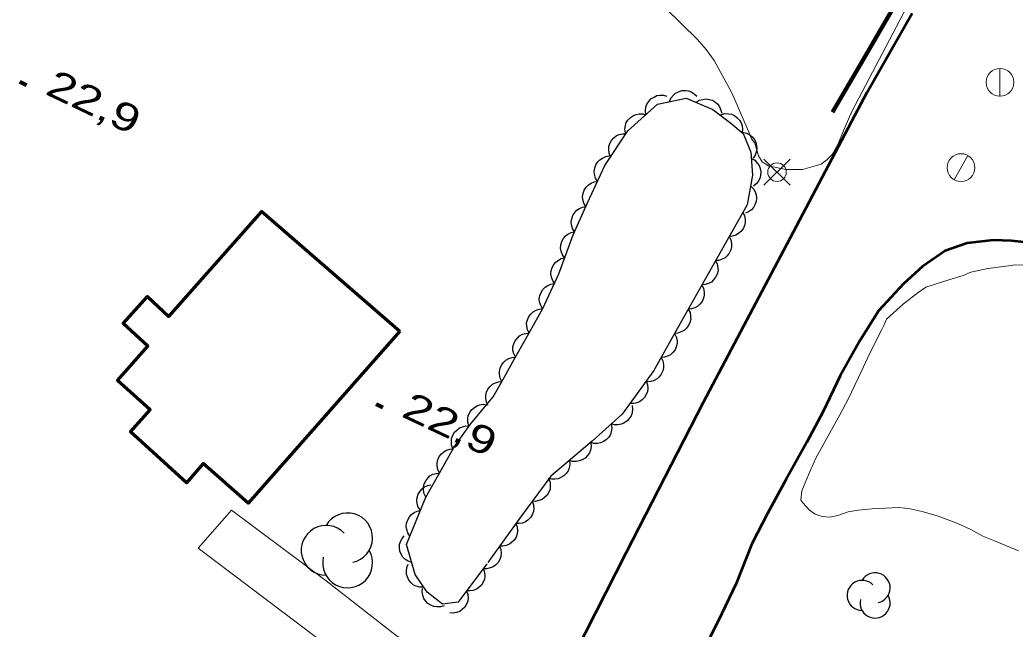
# Model space of a CAD drawing. Extents: x 356765 to 358572, y 5103174 to 5104650.
# Drawn here: x 357232.5 to 357286.2, y 5104019.8 to 5104052.7 of the extents above; entities that cross this region are included whole.
import ezdxf

# ---------------------------------------------------------------- set-up
doc = ezdxf.new("R2010")
doc.units = 0
doc.header["$LTSCALE"] = 0.6
doc.linetypes.add('DOT_DASHED', pattern=[7.7, 5, -1.2, 0.3, -1.2])
doc.linetypes.add('LONG_DASHED', pattern=[7.5, 6, -1.5])
for name, color, linetype, lineweight in [('19', 7, 'Continuous', 13), ('2', 7, 'Continuous', 13), ('21', 7, 'Continuous', 53), ('3', 7, 'Continuous', 140), ('31', 7, 'Continuous', 70), ('36', 7, 'Continuous', 13), ('44', 7, 'Continuous', 25)]:
    doc.layers.add(name, color=color, linetype=linetype, lineweight=lineweight)

msp = doc.modelspace()

# ---------------------------------------------------------------- linework, layer by layer
at = {"layer": '19'}
msp.add_lwpolyline([(357258.19, 5104009.55), (357257.02, 5104011.41), (357255.59, 5104013.33), (357253, 5104015.99), (357242.14, 5104024.2), (357243.93, 5104026.26), (357249.05, 5104022.43), (357252.82, 5104019.49), (357255.94, 5104017.56), (357257.33, 5104016.89), (357258.34, 5104016.43), (357258.98, 5104016.36), (357259.36, 5104016.34), (357259.59, 5104016.41), (357261.4, 5104016.4)], dxfattribs=at)
at = {"layer": '2'}
for points in [[(357271.83, 5104046.76), (357272.01, 5104046.3), (357272.19, 5104046.07), (357272.39, 5104045.38), (357272.58, 5104045.07), (357272.93, 5104044.84), (357273.86, 5104044.65), (357274.76, 5104044.65), (357275.77, 5104044.94), (357276.07, 5104045.18), (357276.37, 5104045.46), (357276.67, 5104046), (357277.06, 5104046.96), (357277.42, 5104047.78), (357280.2, 5104053.05), (357281.49, 5104055.63), (357282.67, 5104057.84), (357283.51, 5104059.57), (357284.25, 5104061.28), (357285.15, 5104063.69), (357286.91, 5104068.94)], [(357286.76, 5104039.48), (357286.21, 5104039.5), (357286.03, 5104039.47), (357284.76, 5104039.3), (357283.85, 5104039.11), (357283.44, 5104038.93), (357282.66, 5104038.7), (357281.42, 5104038.29), (357281, 5104038), (357280.22, 5104037.4), (357279.3, 5104036.57), (357279.15, 5104036.22), (357279.04, 5104036.01), (357278.41, 5104034.76), (357277.79, 5104033.41), (357277.23, 5104032.24), (357276.77, 5104031.4), (357276.14, 5104030.26), (357275.5, 5104029.09), (357275.17, 5104028.38), (357274.72, 5104027.29), (357274.67, 5104026.8), (357274.78, 5104026.65), (357275.14, 5104026.26), (357275.45, 5104026.04), (357275.82, 5104025.91)], [(357286.76, 5104039.48), (357286.21, 5104039.5), (357286.03, 5104039.47), (357284.76, 5104039.3), (357283.85, 5104039.11), (357283.44, 5104038.93), (357282.66, 5104038.7), (357281.42, 5104038.29), (357281, 5104038), (357280.22, 5104037.4), (357279.3, 5104036.57), (357279.15, 5104036.22), (357279.04, 5104036.01), (357278.41, 5104034.76), (357277.79, 5104033.41), (357277.23, 5104032.24), (357276.77, 5104031.4), (357276.14, 5104030.26), (357275.5, 5104029.09), (357275.17, 5104028.38), (357274.72, 5104027.29), (357274.67, 5104026.8), (357274.78, 5104026.65), (357275.14, 5104026.26), (357275.45, 5104026.04), (357275.82, 5104025.91)], [(357275.82, 5104025.91), (357275.82, 5104025.91), (357276.22, 5104025.88), (357276.67, 5104025.97), (357277.23, 5104026.17), (357277.76, 5104026.26), (357278.53, 5104026.32), (357279.96, 5104026.4), (357280.58, 5104026.33), (357281.22, 5104026.19), (357282.08, 5104025.93), (357283.09, 5104025.55), (357283.85, 5104025.21), (357284.5, 5104024.84), (357285.13, 5104024.59), (357286.42, 5104024.05)], [(357275.82, 5104025.91), (357276.22, 5104025.88), (357276.67, 5104025.97), (357277.23, 5104026.17), (357277.76, 5104026.26), (357278.53, 5104026.32), (357279.96, 5104026.4), (357280.58, 5104026.33), (357281.22, 5104026.19), (357282.08, 5104025.93), (357283.09, 5104025.55), (357283.85, 5104025.21), (357284.5, 5104024.84), (357285.13, 5104024.59), (357286.42, 5104024.05)]]:
    msp.add_lwpolyline(points, dxfattribs=at)
at = {"layer": '2', "linetype": 'LONG_DASHED'}
msp.add_lwpolyline([(357267.37, 5104053.37), (357269.1, 5104051.67), (357269.57, 5104051.13), (357269.99, 5104050.53), (357270.95, 5104048.8), (357271.83, 5104046.76)], dxfattribs=at)
at = {"layer": '21', "linetype": 'LONG_DASHED', "lineweight": 140}
msp.add_lwpolyline([(357282.55, 5104058.36), (357281.01, 5104055.71), (357279.47, 5104053.05), (357277.93, 5104050.4), (357276.39, 5104047.75)], dxfattribs=at)
at = {"layer": '21'}
for points in [[(357235, 5103902.34), (357236.8, 5103914.18), (357238.16, 5103922.98), (357240.84, 5103943.53), (357241.93, 5103951.26), (357243.11, 5103959.18), (357244.3, 5103966.44), (357246.54, 5103976.17), (357248.33, 5103983.55), (357249.72, 5103987.87), (357253.83, 5103998.68), (357255.78, 5104004.15), (357260.07, 5104013.78), (357261.4, 5104016.4), (357265.26, 5104023.99), (357269.42, 5104032.09), (357274.09, 5104040.95), (357277.93, 5104048.22), (357278.25, 5104048.83), (357280.69, 5104053.09)], [(357288.05, 5104040.59), (357286.04, 5104040.8), (357285.07, 5104040.84), (357283.66, 5104040.67), (357282.47, 5104040.25), (357281.24, 5104039.41), (357280.21, 5104038.48), (357278.89, 5104037.03), (357277.88, 5104035.43), (357276.79, 5104033.51), (357275.88, 5104031.58), (357274.99, 5104029.92), (357273.86, 5104027.9), (357272.87, 5104026.08), (357272.02, 5104024.43), (357271.18, 5104022.3), (357270.4, 5104020.67), (357269.19, 5104018.19)]]:
    msp.add_lwpolyline(points, dxfattribs=at)
at = {"layer": '3'}
for p, q in [((357232.51, 5104049.38), (357232.87, 5104049.21)), ((357251.74, 5104031.97), (357252.1, 5104031.8))]:
    msp.add_line(p, q, dxfattribs=at)
at = {"layer": '31'}
msp.add_lwpolyline([(357253.03, 5104035.92), (357244.84, 5104026.63), (357242.4, 5104028.78), (357241.51, 5104027.73), (357238.48, 5104030.48), (357239.55, 5104031.67), (357237.78, 5104033.26), (357239.41, 5104035.11), (357238.08, 5104036.34), (357239.4, 5104037.79), (357240.55, 5104036.72), (357245.58, 5104042.38), (357253.03, 5104035.92)], close=True, dxfattribs=at)
at = {"layer": '36'}
for p, q in [((357285.42, 5104048.6), (357285.42, 5104050.1)), ((357282.95, 5104044.1), (357283.69, 5104045.4)), ((357274.09, 5104043.8), (357272.68, 5104045.21)), ((357272.68, 5104043.8), (357274.09, 5104045.21))]:
    msp.add_line(p, q, dxfattribs=at)
for centre, radius in [((357285.4259, 5104049.3604), 0.75), ((357283.3194, 5104044.755), 0.75), ((357273.3868, 5104044.5074), 0.5)]:
    msp.add_circle(centre, radius, dxfattribs=at)
at = {"layer": '44'}
for points in [[(357266.31, 5104047.61), (357266.28, 5104047.82), (357266.31, 5104048.02), (357266.36, 5104048.18), (357266.46, 5104048.33), (357266.58, 5104048.46), (357266.75, 5104048.56), (357266.89, 5104048.64), (357267.07, 5104048.66), (357267.25, 5104048.66), (357267.43, 5104048.62)], [(357267.58, 5104048.31), (357267.66, 5104048.51), (357267.79, 5104048.66), (357267.91, 5104048.78), (357268.07, 5104048.85), (357268.24, 5104048.91), (357268.44, 5104048.91), (357268.6, 5104048.9), (357268.76, 5104048.84), (357268.92, 5104048.74), (357269.05, 5104048.62)], [(357269.02, 5104048.28), (357269.19, 5104048.39), (357269.39, 5104048.44), (357269.55, 5104048.47), (357269.72, 5104048.44), (357269.9, 5104048.39), (357270.06, 5104048.28), (357270.19, 5104048.18), (357270.28, 5104048.03), (357270.36, 5104047.86), (357270.4, 5104047.69)], [(357265.2, 5104046.61), (357265.17, 5104046.82), (357265.2, 5104047.02), (357265.25, 5104047.18), (357265.34, 5104047.32), (357265.47, 5104047.46), (357265.63, 5104047.56), (357265.78, 5104047.63), (357265.95, 5104047.66), (357266.14, 5104047.66), (357266.31, 5104047.61)], [(357270.36, 5104047.61), (357270.56, 5104047.67), (357270.76, 5104047.66), (357270.93, 5104047.64), (357271.09, 5104047.56), (357271.24, 5104047.45), (357271.36, 5104047.31), (357271.45, 5104047.17), (357271.5, 5104047), (357271.52, 5104046.82), (357271.5, 5104046.64)], [(357264.4, 5104045.33), (357264.32, 5104045.53), (357264.3, 5104045.73), (357264.31, 5104045.89), (357264.36, 5104046.06), (357264.45, 5104046.22), (357264.58, 5104046.36), (357264.71, 5104046.47), (357264.87, 5104046.54), (357265.05, 5104046.58), (357265.23, 5104046.58)], [(357271.53, 5104046.66), (357271.74, 5104046.62), (357271.91, 5104046.52), (357272.05, 5104046.42), (357272.15, 5104046.28), (357272.24, 5104046.12), (357272.28, 5104045.93), (357272.3, 5104045.77), (357272.26, 5104045.59), (357272.2, 5104045.42), (357272.1, 5104045.27)], [(357263.7, 5104044.01), (357263.59, 5104044.19), (357263.54, 5104044.39), (357263.52, 5104044.55), (357263.55, 5104044.73), (357263.61, 5104044.9), (357263.72, 5104045.06), (357263.82, 5104045.18), (357263.97, 5104045.27), (357264.14, 5104045.35), (357264.32, 5104045.38)], [(357272, 5104045.25), (357272.18, 5104045.15), (357272.32, 5104045), (357272.42, 5104044.87), (357272.48, 5104044.7), (357272.51, 5104044.52), (357272.49, 5104044.33), (357272.46, 5104044.17), (357272.37, 5104044.01), (357272.26, 5104043.87), (357272.12, 5104043.75)], [(357263.07, 5104042.65), (357262.96, 5104042.83), (357262.91, 5104043.03), (357262.89, 5104043.19), (357262.92, 5104043.36), (357262.98, 5104043.54), (357263.09, 5104043.7), (357263.2, 5104043.82), (357263.35, 5104043.91), (357263.52, 5104043.98), (357263.7, 5104044.01)], [(357271.96, 5104043.76), (357272.11, 5104043.61), (357272.2, 5104043.44), (357272.26, 5104043.28), (357272.28, 5104043.11), (357272.26, 5104042.92), (357272.19, 5104042.74), (357272.12, 5104042.6), (357272, 5104042.47), (357271.85, 5104042.36), (357271.68, 5104042.29)], [(357262.45, 5104041.28), (357262.34, 5104041.46), (357262.29, 5104041.66), (357262.27, 5104041.82), (357262.3, 5104041.99), (357262.36, 5104042.17), (357262.47, 5104042.33), (357262.57, 5104042.45), (357262.72, 5104042.55), (357262.89, 5104042.62), (357263.07, 5104042.65)], [(357271.54, 5104042.34), (357271.63, 5104042.15), (357271.67, 5104041.95), (357271.67, 5104041.79), (357271.63, 5104041.62), (357271.55, 5104041.45), (357271.43, 5104041.3), (357271.31, 5104041.19), (357271.16, 5104041.1), (357270.98, 5104041.05), (357270.8, 5104041.03)], [(357261.92, 5104039.88), (357261.8, 5104040.05), (357261.73, 5104040.24), (357261.7, 5104040.4), (357261.72, 5104040.58), (357261.77, 5104040.76), (357261.86, 5104040.92), (357261.96, 5104041.06), (357262.1, 5104041.16), (357262.27, 5104041.24), (357262.44, 5104041.29)], [(357270.8, 5104041.03), (357270.89, 5104040.85), (357270.93, 5104040.65), (357270.93, 5104040.48), (357270.89, 5104040.31), (357270.81, 5104040.14), (357270.69, 5104039.99), (357270.58, 5104039.88), (357270.42, 5104039.8), (357270.24, 5104039.74), (357270.06, 5104039.73)], [(357261.4, 5104038.47), (357261.28, 5104038.64), (357261.21, 5104038.84), (357261.18, 5104039), (357261.2, 5104039.17), (357261.25, 5104039.35), (357261.34, 5104039.52), (357261.44, 5104039.65), (357261.58, 5104039.75), (357261.74, 5104039.84), (357261.92, 5104039.88)], [(357270.06, 5104039.73), (357270.16, 5104039.54), (357270.19, 5104039.34), (357270.2, 5104039.17), (357270.15, 5104039), (357270.07, 5104038.84), (357269.95, 5104038.69), (357269.84, 5104038.57), (357269.68, 5104038.49), (357269.51, 5104038.44), (357269.33, 5104038.42)], [(357260.73, 5104037.13), (357260.63, 5104037.3), (357260.57, 5104037.5), (357260.55, 5104037.67), (357260.58, 5104037.84), (357260.65, 5104038.01), (357260.75, 5104038.17), (357260.86, 5104038.3), (357261.01, 5104038.39), (357261.18, 5104038.46), (357261.36, 5104038.49)], [(357269.33, 5104038.42), (357269.42, 5104038.23), (357269.45, 5104038.03), (357269.46, 5104037.87), (357269.42, 5104037.7), (357269.34, 5104037.53), (357269.22, 5104037.38), (357269.11, 5104037.27), (357268.95, 5104037.18), (357268.77, 5104037.13), (357268.59, 5104037.11)], [(357260, 5104035.82), (357259.91, 5104036.01), (357259.87, 5104036.21), (357259.86, 5104036.37), (357259.91, 5104036.54), (357259.98, 5104036.71), (357260.11, 5104036.86), (357260.22, 5104036.97), (357260.38, 5104037.05), (357260.55, 5104037.11), (357260.73, 5104037.13)], [(357268.59, 5104037.11), (357268.69, 5104036.93), (357268.72, 5104036.73), (357268.73, 5104036.56), (357268.68, 5104036.39), (357268.61, 5104036.22), (357268.49, 5104036.07), (357268.37, 5104035.96), (357268.22, 5104035.88), (357268.04, 5104035.82), (357267.86, 5104035.8)], [(357259.26, 5104034.51), (357259.17, 5104034.7), (357259.13, 5104034.9), (357259.13, 5104035.07), (357259.17, 5104035.24), (357259.25, 5104035.4), (357259.37, 5104035.55), (357259.49, 5104035.67), (357259.64, 5104035.75), (357259.82, 5104035.8), (357260, 5104035.82)], [(357267.86, 5104035.8), (357267.95, 5104035.62), (357267.99, 5104035.42), (357268, 5104035.25), (357267.95, 5104035.08), (357267.88, 5104034.91), (357267.76, 5104034.76), (357267.64, 5104034.65), (357267.48, 5104034.57), (357267.31, 5104034.51), (357267.13, 5104034.49)], [(357258.53, 5104033.2), (357258.44, 5104033.39), (357258.4, 5104033.59), (357258.4, 5104033.75), (357258.44, 5104033.92), (357258.51, 5104034.09), (357258.63, 5104034.24), (357258.75, 5104034.36), (357258.9, 5104034.44), (357259.08, 5104034.5), (357259.26, 5104034.51)], [(357267.13, 5104034.49), (357267.22, 5104034.31), (357267.26, 5104034.11), (357267.26, 5104033.94), (357267.22, 5104033.77), (357267.14, 5104033.6), (357267.02, 5104033.45), (357266.91, 5104033.34), (357266.75, 5104033.26), (357266.58, 5104033.2), (357266.4, 5104033.19)], [(357257.79, 5104031.9), (357257.7, 5104032.08), (357257.67, 5104032.28), (357257.66, 5104032.45), (357257.71, 5104032.62), (357257.78, 5104032.79), (357257.9, 5104032.94), (357258.02, 5104033.05), (357258.18, 5104033.13), (357258.35, 5104033.19), (357258.53, 5104033.2)], [(357266.33, 5104033.23), (357266.4, 5104033.03), (357266.41, 5104032.83), (357266.4, 5104032.67), (357266.33, 5104032.5), (357266.24, 5104032.34), (357266.1, 5104032.21), (357265.97, 5104032.11), (357265.81, 5104032.05), (357265.63, 5104032.01), (357265.45, 5104032.02)], [(357256.75, 5104030.8), (357256.7, 5104031), (357256.7, 5104031.2), (357256.72, 5104031.36), (357256.8, 5104031.52), (357256.9, 5104031.68), (357257.05, 5104031.8), (357257.18, 5104031.89), (357257.35, 5104031.94), (357257.53, 5104031.97), (357257.71, 5104031.95)], [(357265.56, 5104031.91), (357265.59, 5104031.71), (357265.56, 5104031.51), (357265.51, 5104031.35), (357265.41, 5104031.2), (357265.29, 5104031.07), (357265.12, 5104030.96), (357264.98, 5104030.89), (357264.8, 5104030.87), (357264.62, 5104030.87), (357264.44, 5104030.91)], [(357264.44, 5104030.91), (357264.47, 5104030.7), (357264.44, 5104030.5), (357264.39, 5104030.34), (357264.3, 5104030.2), (357264.17, 5104030.06), (357264.01, 5104029.96), (357263.86, 5104029.89), (357263.69, 5104029.86), (357263.5, 5104029.86), (357263.33, 5104029.91)], [(357255.89, 5104029.57), (357255.82, 5104029.77), (357255.81, 5104029.97), (357255.82, 5104030.13), (357255.88, 5104030.3), (357255.97, 5104030.46), (357256.11, 5104030.59), (357256.24, 5104030.7), (357256.4, 5104030.76), (357256.58, 5104030.8), (357256.76, 5104030.79)], [(357263.33, 5104029.91), (357263.35, 5104029.7), (357263.31, 5104029.5), (357263.26, 5104029.35), (357263.16, 5104029.2), (357263.03, 5104029.07), (357262.86, 5104028.97), (357262.71, 5104028.91), (357262.54, 5104028.88), (357262.35, 5104028.89), (357262.18, 5104028.94)], [(357255.16, 5104028.26), (357255.07, 5104028.45), (357255.04, 5104028.65), (357255.03, 5104028.81), (357255.07, 5104028.98), (357255.15, 5104029.15), (357255.27, 5104029.3), (357255.39, 5104029.41), (357255.54, 5104029.49), (357255.72, 5104029.55), (357255.9, 5104029.57)], [(357262.18, 5104028.94), (357262.2, 5104028.73), (357262.16, 5104028.53), (357262.11, 5104028.38), (357262.01, 5104028.23), (357261.88, 5104028.1), (357261.72, 5104028.01), (357261.57, 5104027.94), (357261.39, 5104027.92), (357261.21, 5104027.93), (357261.03, 5104027.97)], [(357254.43, 5104026.95), (357254.34, 5104027.14), (357254.3, 5104027.34), (357254.3, 5104027.5), (357254.34, 5104027.67), (357254.42, 5104027.84), (357254.54, 5104027.99), (357254.65, 5104028.11), (357254.81, 5104028.19), (357254.98, 5104028.24), (357255.16, 5104028.26)], [(357254.14, 5104026.23), (357254.02, 5104026.41), (357253.96, 5104026.6), (357253.94, 5104026.77), (357253.96, 5104026.94), (357254.01, 5104027.12), (357254.12, 5104027.28), (357254.22, 5104027.41), (357254.36, 5104027.51), (357254.53, 5104027.59), (357254.7, 5104027.62)], [(357261.06, 5104027.95), (357261.13, 5104027.75), (357261.14, 5104027.55), (357261.13, 5104027.38), (357261.06, 5104027.22), (357260.97, 5104027.06), (357260.83, 5104026.93), (357260.7, 5104026.83), (357260.53, 5104026.77), (357260.35, 5104026.73), (357260.17, 5104026.74)], [(357260.17, 5104026.74), (357260.24, 5104026.54), (357260.25, 5104026.34), (357260.24, 5104026.18), (357260.17, 5104026.01), (357260.08, 5104025.85), (357259.94, 5104025.72), (357259.81, 5104025.62), (357259.64, 5104025.56), (357259.46, 5104025.53), (357259.28, 5104025.53)], [(357253.57, 5104024.85), (357253.46, 5104025.02), (357253.4, 5104025.21), (357253.37, 5104025.38), (357253.39, 5104025.55), (357253.45, 5104025.73), (357253.55, 5104025.89), (357253.65, 5104026.02), (357253.79, 5104026.12), (357253.96, 5104026.2), (357254.14, 5104026.23)], [(357259.29, 5104025.53), (357259.36, 5104025.33), (357259.37, 5104025.13), (357259.36, 5104024.97), (357259.3, 5104024.8), (357259.2, 5104024.64), (357259.06, 5104024.51), (357258.94, 5104024.41), (357258.77, 5104024.34), (357258.59, 5104024.31), (357258.41, 5104024.31)], [(357253.67, 5104023.42), (357253.47, 5104023.49), (357253.3, 5104023.6), (357253.18, 5104023.71), (357253.09, 5104023.87), (357253.03, 5104024.04), (357253.01, 5104024.23), (357253.01, 5104024.39), (357253.06, 5104024.56), (357253.14, 5104024.73), (357253.26, 5104024.86)], [(357258.41, 5104024.31), (357258.48, 5104024.12), (357258.49, 5104023.91), (357258.48, 5104023.75), (357258.42, 5104023.58), (357258.33, 5104023.43), (357258.19, 5104023.29), (357258.06, 5104023.19), (357257.9, 5104023.13), (357257.72, 5104023.09), (357257.54, 5104023.09)], [(357254.32, 5104022.09), (357254.11, 5104022.09), (357253.91, 5104022.15), (357253.76, 5104022.21), (357253.63, 5104022.33), (357253.51, 5104022.47), (357253.43, 5104022.65), (357253.38, 5104022.8), (357253.38, 5104022.98), (357253.4, 5104023.16), (357253.47, 5104023.33)], [(357257.53, 5104023.1), (357257.6, 5104022.9), (357257.61, 5104022.7), (357257.59, 5104022.53), (357257.53, 5104022.37), (357257.43, 5104022.21), (357257.29, 5104022.08), (357257.16, 5104021.98), (357256.99, 5104021.92), (357256.81, 5104021.89), (357256.63, 5104021.9)], [(357255.42, 5104021.09), (357255.22, 5104021.03), (357255.02, 5104021.03), (357254.85, 5104021.05), (357254.69, 5104021.12), (357254.54, 5104021.22), (357254.41, 5104021.36), (357254.31, 5104021.49), (357254.26, 5104021.66), (357254.23, 5104021.84), (357254.24, 5104022.02)], [(357256.63, 5104021.9), (357256.7, 5104021.7), (357256.71, 5104021.5), (357256.69, 5104021.33), (357256.63, 5104021.17), (357256.53, 5104021.01), (357256.39, 5104020.88), (357256.26, 5104020.78), (357256.09, 5104020.72), (357255.91, 5104020.69), (357255.73, 5104020.7)]]:
    msp.add_lwpolyline(points, dxfattribs=at)
at = {"layer": '44', "linetype": 'DOT_DASHED'}
msp.add_lwpolyline([(357254.43, 5104026.95), (357255.18, 5104028.29), (357255.94, 5104029.64), (357256.84, 5104030.9), (357258.06, 5104032.37), (357258.65, 5104033.41), (357259.23, 5104034.46), (357259.82, 5104035.5), (357260.74, 5104037.14), (357261.6, 5104039.02), (357262.38, 5104041.12), (357263.16, 5104042.85), (357264.09, 5104044.87), (357265.33, 5104046.73), (357266.94, 5104048.18), (357268.49, 5104048.5), (357269.92, 5104047.89), (357270.89, 5104047.16), (357271.56, 5104046.59), (357271.97, 5104045.58), (357272.07, 5104044.35), (357271.77, 5104042.75), (357270.76, 5104040.96), (357269.5, 5104038.73), (357268.16, 5104036.34), (357266.74, 5104033.8), (357265.02, 5104031.43), (357263.41, 5104029.98), (357261.17, 5104028.09), (357259.53, 5104025.87), (357257.72, 5104023.35), (357256.17, 5104021.28), (357255.32, 5104021.17), (357254.5, 5104021.82), (357253.85, 5104022.77), (357253.39, 5104024.4)], close=True, dxfattribs=at)
at = {"layer": '44'}
for centre, radius, start, end in [((357250.2024, 5104024.7538), 1.3465, 282.26917, 149.72626), ((357249.0444, 5104024.0806), 1.3465, 44.11537, 269.80396), ((357250.2024, 5104023.4073), 1.3465, 166.93686, 29.62122), ((357278.6799, 5104022.0553), 0.8137, 282.26917, 149.72626), ((357277.9801, 5104021.6485), 0.8137, 44.11537, 269.80396), ((357278.6799, 5104021.2416), 0.8137, 166.93686, 29.62122)]:
    msp.add_arc(centre, radius, start, end, dxfattribs=at)

# ---------------------------------------------------------------- texts
at = {"layer": '3', "width": 1.35}
for p in [(357233.81, 5104048.75), (357253.04, 5104031.34)]:
    msp.add_text('22,9   ', height=1.5, rotation=334.619, dxfattribs=at).set_placement(p)

doc.saveas('drawing.dxf')
